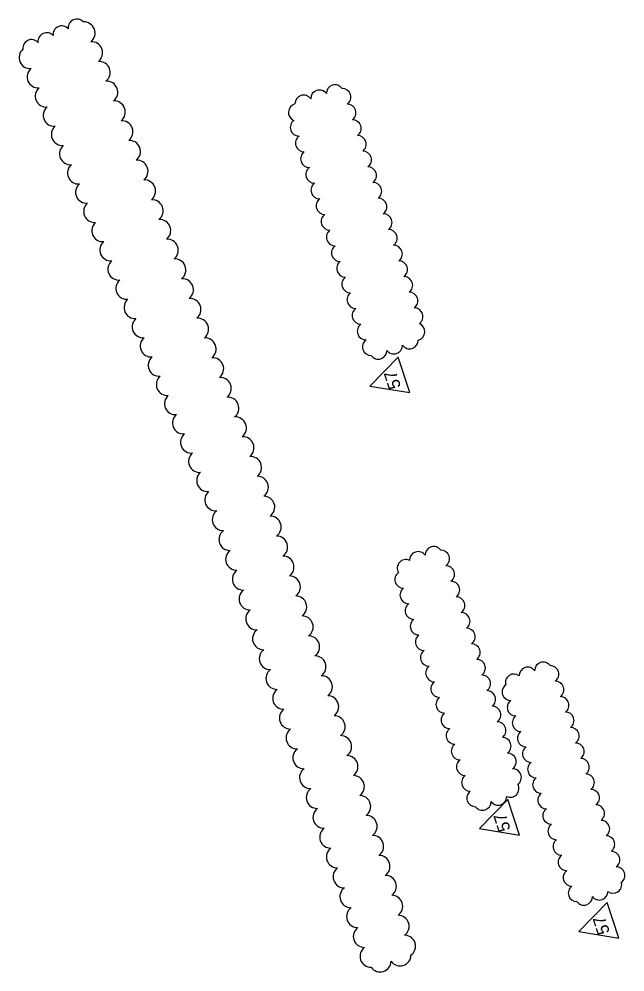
# Model space of a CAD drawing. Extents: x 929207 to 930387, y 631822 to 633132.
# Drawn here: x 929207 to 929479.7, y 632156.3 to 632585.7 of the extents above; entities that cross this region are included whole.
import ezdxf

# ---------------------------------------------------------------- set-up
doc = ezdxf.new("R2010")
doc.units = 0
doc.layers.add('PoleLight', color=7, linetype='Continuous')

msp = doc.modelspace()

# ---------------------------------------------------------------- linework, layer by layer
at = {"layer": 'PoleLight'}
for points in [[(929364.88, 632420.29), (929382.98, 632417.34), (929377.71, 632433.4)], [(929414.24, 632220.91), (929432.34, 632217.96), (929427.07, 632234.02)], [(929458.93, 632174.58), (929477.03, 632171.63), (929471.76, 632187.69)]]:
    msp.add_lwpolyline(points, close=True, dxfattribs=at)
for centre, radius, start, end in [((929226.2, 632578.67), 3.91, 41.9251, 186.9251), ((929233, 632581.76), 3.91, 41.9251, 186.9251), ((929236.21, 632579.38), 5, 308.4491, 93.4491), ((929219.41, 632575.59), 3.91, 41.9251, 186.9251), ((929212.62, 632572.5), 3.91, 41.9251, 186.9251), ((929239.61, 632570.49), 5, 308.4491, 93.4491), ((929211.92, 632568.27), 4.93, 130.2631, 275.2631), ((929243.02, 632561.59), 5, 308.4491, 93.4491), ((929215.56, 632559.61), 4.93, 130.2631, 275.2631), ((929246.43, 632552.69), 5, 308.4491, 93.4491), ((929219.19, 632550.95), 4.93, 130.2631, 275.2631), ((929342.17, 632549.79), 3.9, 35.6866, 180.6866), ((929349.23, 632552.11), 3.9, 35.6866, 180.6866), ((929352.44, 632550.49), 3.9, 305.6866, 90.6866), ((929249.83, 632543.79), 5, 308.4491, 93.4491), ((929335.11, 632547.47), 3.9, 35.6866, 180.6866), ((929222.83, 632542.29), 4.93, 130.2631, 275.2631), ((929332.13, 632543.64), 3.9, 103.7186, 248.7186), ((929354.77, 632543.43), 3.9, 305.6866, 90.6866), ((929253.24, 632534.89), 5, 308.4491, 93.4491), ((929332.99, 632536.85), 3.9, 125.6866, 270.6866), ((929357.09, 632536.37), 3.9, 305.6866, 90.6866), ((929226.46, 632533.62), 4.93, 130.2631, 275.2631), ((929256.65, 632525.99), 5, 308.4491, 93.4491), ((929335.31, 632529.78), 3.9, 125.6866, 270.6866), ((929359.41, 632529.3), 3.9, 305.6866, 90.6866), ((929230.1, 632524.96), 4.93, 130.2631, 275.2631), ((929337.63, 632522.72), 3.9, 125.6866, 270.6866), ((929361.73, 632522.24), 3.9, 305.6866, 90.6866), ((929233.73, 632516.3), 4.93, 130.2631, 275.2631), ((929260.05, 632517.09), 5, 308.4491, 93.4491), ((929339.95, 632515.66), 3.9, 125.6866, 270.6866), ((929364.05, 632515.18), 3.9, 305.6866, 90.6866), ((929237.37, 632507.64), 4.93, 130.2631, 275.2631), ((929263.46, 632508.2), 5, 308.4491, 93.4491), ((929342.28, 632508.6), 3.9, 125.6866, 270.6866), ((929366.37, 632508.12), 3.9, 305.6866, 90.6866), ((929241, 632498.97), 4.93, 130.2631, 275.2631), ((929266.87, 632499.3), 5, 308.4491, 93.4491), ((929344.6, 632501.53), 3.9, 125.6866, 270.6866), ((929368.69, 632501.05), 3.9, 305.6866, 90.6866), ((929346.92, 632494.47), 3.9, 125.6866, 270.6866), ((929371.01, 632493.99), 3.9, 305.6866, 90.6866), ((929244.64, 632490.31), 4.93, 130.2631, 275.2631), ((929270.27, 632490.4), 5, 308.4491, 93.4491), ((929349.24, 632487.41), 3.9, 125.6866, 270.6866), ((929373.33, 632486.93), 3.9, 305.6866, 90.6866), ((929248.27, 632481.65), 4.93, 130.2631, 275.2631), ((929273.68, 632481.5), 5, 308.4491, 93.4491), ((929375.65, 632479.87), 3.9, 305.6866, 90.6866), ((929351.56, 632480.35), 3.9, 125.6866, 270.6866), ((929251.91, 632472.98), 4.93, 130.2631, 275.2631), ((929277.09, 632472.6), 5, 308.4491, 93.4491), ((929353.88, 632473.28), 3.9, 125.6866, 270.6866), ((929377.97, 632472.8), 3.9, 305.6866, 90.6866), ((929255.54, 632464.32), 4.93, 130.2631, 275.2631), ((929280.49, 632463.7), 5, 308.4491, 93.4491), ((929356.2, 632466.22), 3.9, 125.6866, 270.6866), ((929380.29, 632465.74), 3.9, 305.6866, 90.6866), ((929358.52, 632459.16), 3.9, 125.6866, 270.6866), ((929382.61, 632458.68), 3.9, 305.6866, 90.6866), ((929259.18, 632455.66), 4.93, 130.2631, 275.2631), ((929283.9, 632454.8), 5, 308.4491, 93.4491), ((929360.84, 632452.1), 3.9, 125.6866, 270.6866), ((929384.93, 632451.62), 3.9, 305.6866, 90.6866), ((929262.81, 632447), 4.93, 130.2631, 275.2631), ((929287.31, 632445.91), 5, 308.4491, 93.4491), ((929363.16, 632445.03), 3.9, 125.6866, 270.6866), ((929385.79, 632444.82), 3.9, 283.7186, 68.7186), ((929266.44, 632438.33), 4.93, 130.2631, 275.2631), ((929290.71, 632437.01), 5, 308.4491, 93.4491), ((929365.48, 632437.97), 3.9, 125.6866, 270.6866), ((929382.81, 632440.99), 3.9, 215.6866, 0.6866), ((929375.75, 632438.67), 3.9, 215.6866, 0.6866), ((929270.08, 632429.67), 4.93, 130.2631, 275.2631), ((929294.12, 632428.11), 5, 308.4491, 93.4491), ((929368.69, 632436.35), 3.9, 215.6866, 0.6866), ((929273.71, 632421.01), 4.93, 130.2631, 275.2631), ((929297.53, 632419.21), 5, 308.4491, 93.4491), ((929277.35, 632412.35), 4.93, 130.2631, 275.2631), ((929300.94, 632410.31), 5, 308.4491, 93.4491), ((929280.98, 632403.68), 4.93, 130.2631, 275.2631), ((929304.34, 632401.41), 5, 308.4491, 93.4491), ((929284.62, 632395.02), 4.93, 130.2631, 275.2631), ((929307.75, 632392.51), 5, 308.4491, 93.4491), ((929288.25, 632386.36), 4.93, 130.2631, 275.2631), ((929311.16, 632383.62), 5, 308.4491, 93.4491), ((929291.89, 632377.7), 4.93, 130.2631, 275.2631), ((929314.28, 632374.75), 4.95, 305.2653, 90.2653), ((929295.52, 632369.03), 4.93, 130.2631, 275.2631), ((929317.17, 632365.76), 4.95, 305.2653, 90.2653), ((929298.9, 632360.14), 4.95, 126.1868, 271.1868), ((929320.05, 632356.77), 4.95, 305.2653, 90.2653), ((929301.92, 632351.19), 4.95, 126.1868, 271.1868), ((929322.93, 632347.78), 4.95, 305.2653, 90.2653), ((929393.67, 632344.15), 3.88, 35.6866, 180.6866), ((929396.87, 632342.53), 3.88, 305.6866, 90.6866), ((929304.95, 632342.25), 4.95, 126.1868, 271.1868), ((929325.81, 632338.79), 4.95, 305.2653, 90.2653), ((929381.14, 632338.27), 3.88, 65.2768, 210.2768), ((929386.64, 632341.84), 3.88, 35.6866, 180.6866), ((929399.18, 632335.5), 3.88, 305.6866, 90.6866), ((929307.97, 632333.31), 4.95, 126.1868, 271.1868), ((929328.69, 632329.8), 4.95, 305.2653, 90.2653), ((929380.05, 632333.16), 3.88, 125.6866, 270.6866), ((929382.36, 632326.12), 3.88, 125.6866, 270.6866), ((929401.5, 632328.46), 3.88, 305.6866, 90.6866), ((929310.99, 632324.37), 4.95, 126.1868, 271.1868), ((929331.57, 632320.8), 4.95, 305.2653, 90.2653), ((929403.81, 632321.43), 3.88, 305.6866, 90.6866), ((929384.67, 632319.09), 3.88, 125.6866, 270.6866), ((929314.02, 632315.43), 4.95, 126.1868, 271.1868), ((929334.45, 632311.81), 4.95, 305.2653, 90.2653), ((929406.12, 632314.39), 3.88, 305.6866, 90.6866), ((929386.98, 632312.06), 3.88, 125.6866, 270.6866), ((929317.04, 632306.49), 4.95, 126.1868, 271.1868), ((929337.33, 632302.82), 4.95, 305.2653, 90.2653), ((929389.29, 632305.02), 3.88, 125.6866, 270.6866), ((929408.43, 632307.36), 3.88, 305.6866, 90.6866), ((929410.74, 632300.32), 3.88, 305.6866, 90.6866), ((929320.07, 632297.54), 4.95, 126.1868, 271.1868), ((929391.61, 632297.99), 3.88, 125.6866, 270.6866), ((929340.21, 632293.83), 4.95, 305.2653, 90.2653), ((929413.05, 632293.29), 3.88, 305.6866, 90.6866), ((929442.96, 632292.1), 3.85, 35.6866, 180.6866), ((929323.09, 632288.6), 4.95, 126.1868, 271.1868), ((929393.92, 632290.95), 3.88, 125.6866, 270.6866), ((929429.76, 632286.74), 3.84, 51.7128, 196.7128), ((929435.99, 632289.81), 3.85, 35.6866, 180.6866), ((929446.13, 632290.49), 3.85, 305.6866, 90.6866), ((929343.09, 632284.84), 4.95, 305.2653, 90.2653), ((929396.23, 632283.92), 3.88, 125.6866, 270.6866), ((929415.36, 632286.25), 3.88, 305.6866, 90.6866), ((929448.42, 632283.52), 3.85, 305.6866, 90.6866), ((929326.12, 632279.66), 4.95, 126.1868, 271.1868), ((929417.67, 632279.22), 3.88, 305.6866, 90.6866), ((929428.32, 632282.51), 3.85, 125.6866, 270.6866), ((929345.97, 632275.85), 4.95, 305.2653, 90.2653), ((929398.54, 632276.88), 3.88, 125.6866, 270.6866), ((929430.61, 632275.54), 3.85, 125.6866, 270.6866), ((929450.71, 632276.55), 3.85, 305.6866, 90.6866), ((929329.14, 632270.72), 4.95, 126.1868, 271.1868), ((929419.98, 632272.18), 3.88, 305.6866, 90.6866), ((929453, 632269.58), 3.85, 305.6866, 90.6866), ((929348.85, 632266.85), 4.95, 305.2653, 90.2653), ((929400.85, 632269.85), 3.88, 125.6866, 270.6866), ((929422.3, 632265.15), 3.88, 305.6866, 90.6866), ((929432.9, 632268.57), 3.85, 125.6866, 270.6866), ((929332.16, 632261.78), 4.95, 126.1868, 271.1868), ((929403.16, 632262.81), 3.88, 125.6866, 270.6866), ((929455.29, 632262.61), 3.85, 305.6866, 90.6866), ((929351.74, 632257.86), 4.95, 305.2653, 90.2653), ((929424.61, 632258.12), 3.88, 305.6866, 90.6866), ((929435.19, 632261.6), 3.85, 125.6866, 270.6866), ((929335.19, 632252.84), 4.95, 126.1868, 271.1868), ((929405.47, 632255.78), 3.88, 125.6866, 270.6866), ((929437.48, 632254.63), 3.85, 125.6866, 270.6866), ((929457.58, 632255.64), 3.85, 305.6866, 90.6866), ((929354.62, 632248.87), 4.95, 305.2653, 90.2653), ((929407.78, 632248.74), 3.88, 125.6866, 270.6866), ((929426.92, 632251.08), 3.88, 305.6866, 90.6866), ((929459.87, 632248.67), 3.85, 305.6866, 90.6866), ((929338.21, 632243.9), 4.95, 126.1868, 271.1868), ((929429.23, 632244.05), 3.88, 305.6866, 90.6866), ((929439.77, 632247.66), 3.85, 125.6866, 270.6866), ((929357.5, 632239.88), 4.95, 305.2653, 90.2653), ((929410.09, 632241.71), 3.88, 125.6866, 270.6866), ((929442.06, 632240.69), 3.85, 125.6866, 270.6866), ((929462.16, 632241.7), 3.85, 305.6866, 90.6866), ((929428.14, 632238.94), 3.88, 245.2768, 30.2768), ((929341.24, 632234.95), 4.95, 126.1868, 271.1868), ((929360.38, 632230.89), 4.95, 305.2653, 90.2653), ((929412.41, 632234.67), 3.88, 125.6866, 270.6866), ((929422.64, 632235.37), 3.88, 215.6866, 0.6866), ((929444.35, 632233.72), 3.85, 125.6866, 270.6866), ((929464.45, 632234.73), 3.85, 305.6866, 90.6866), ((929415.61, 632233.06), 3.88, 215.6866, 0.6866), ((929466.74, 632227.76), 3.85, 305.6866, 90.6866), ((929344.26, 632226.01), 4.95, 126.1868, 271.1868), ((929363.26, 632221.9), 4.95, 305.2653, 90.2653), ((929446.64, 632226.75), 3.85, 125.6866, 270.6866), ((929448.93, 632219.78), 3.85, 125.6866, 270.6866), ((929469.03, 632220.79), 3.85, 305.6866, 90.6866), ((929347.29, 632217.07), 4.95, 126.1868, 271.1868), ((929366.14, 632212.9), 4.95, 305.2653, 90.2653), ((929471.32, 632213.82), 3.85, 305.6866, 90.6866), ((929451.22, 632212.81), 3.85, 125.6866, 270.6866), ((929350.31, 632208.13), 4.95, 126.1868, 271.1868), ((929453.51, 632205.83), 3.85, 125.6866, 270.6866), ((929473.61, 632206.84), 3.85, 305.6866, 90.6866), ((929369.02, 632203.91), 4.95, 305.2653, 90.2653), ((929353.33, 632199.19), 4.95, 126.1868, 271.1868), ((929455.8, 632198.86), 3.85, 125.6866, 270.6866), ((929475.9, 632199.87), 3.85, 305.6866, 90.6866), ((929371.9, 632194.92), 4.95, 305.2653, 90.2653), ((929474.46, 632195.64), 3.84, 231.7128, 16.7128), ((929356.36, 632190.25), 4.95, 126.1868, 271.1868), ((929458.09, 632191.89), 3.85, 125.6866, 270.6866), ((929468.23, 632192.58), 3.85, 215.6866, 0.6866), ((929374.78, 632185.93), 4.95, 305.2653, 90.2653), ((929461.26, 632190.29), 3.85, 215.6866, 0.6866), ((929359.38, 632181.3), 4.95, 126.1868, 271.1868), ((929377.66, 632176.94), 4.95, 305.2653, 90.2653), ((929362.41, 632172.36), 4.95, 126.1868, 271.1868), ((929380.54, 632167.95), 4.95, 305.2653, 90.2653), ((929365.43, 632163.42), 4.95, 126.1868, 271.1868), ((929378.51, 632163.96), 4.9, 214.4066, 359.4066), ((929369.57, 632161.24), 4.9, 214.4066, 359.4066)]:
    msp.add_arc(centre, radius, start, end, dxfattribs=at)

# ---------------------------------------------------------------- texts
for p in [(929379, 632419.95), (929428.36, 632220.57), (929473.04, 632174.24)]:
    msp.add_text('57', height=5.6, rotation=108.1866, dxfattribs=at).set_placement(p)

doc.saveas('drawing.dxf')
